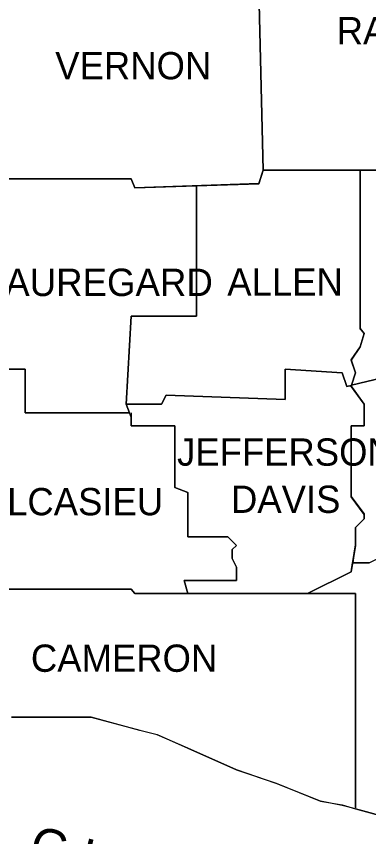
# Model space of a CAD drawing. Extents: x 0.19 to 2.82, y 0.04 to 1.79.
# Drawn here: x 2.26 to 2.3204, y 1.4533 to 1.594 of the extents above; entities that cross this region are included whole.
import ezdxf

# ---------------------------------------------------------------- set-up
doc = ezdxf.new("R2010")
doc.units = 0
for name, color, linetype in [('Dist03', 7, 'Continuous'), ('Dist07', 7, 'Continuous'), ('Dist08', 7, 'Continuous'), ('Standard Info', 7, 'Continuous')]:
    doc.layers.add(name, color=color, linetype=linetype)

msp = doc.modelspace()

# ---------------------------------------------------------------- linework, layer by layer
at = {"layer": 'Dist03'}
for points in [[(2.3469, 1.56308), (2.3454, 1.56308), (2.3454, 1.56758), (2.3439, 1.56917), (2.3424, 1.57067), (2.3424, 1.57292), (2.34015, 1.57292), (2.33782, 1.57292), (2.33557, 1.57367), (2.33482, 1.57592), (2.33407, 1.57592), (2.33257, 1.57517), (2.33182, 1.57367), (2.33024, 1.57217), (2.32799, 1.57067), (2.32649, 1.56758), (2.31899, 1.56758)], [(2.31899, 1.56758), (2.31899, 1.54042), (2.31965, 1.53958), (2.31899, 1.53733), (2.3174, 1.53508), (2.31815, 1.53283), (2.3174, 1.53058)], [(2.31732, 1.53075), (2.31965, 1.5275), (2.31965, 1.526), (2.31965, 1.52375), (2.3174, 1.52375), (2.3174, 1.51167), (2.31965, 1.50867), (2.31965, 1.50783), (2.31815, 1.50633), (2.31815, 1.50333), (2.3174, 1.49875), (2.3099, 1.495)], [(2.3099, 1.495), (2.31815, 1.495), (2.31815, 1.45833)], [(2.31815, 1.45808), (2.32424, 1.45642), (2.33257, 1.45725), (2.34015, 1.45492), (2.34165, 1.45492), (2.3469, 1.45642), (2.34765, 1.45642)]]:
    msp.add_lwpolyline(points, dxfattribs=at)
at = {"layer": 'Dist07'}
for points in [[(2.30232, 1.56758), (2.30157, 1.56533), (2.28032, 1.56458), (2.27965, 1.56608), (2.25765, 1.56608), (2.2539, 1.56383), (2.25007, 1.56683), (2.2494, 1.56533)], [(2.31899, 1.56758), (2.30232, 1.56758)], [(2.3174, 1.53058), (2.31815, 1.53283), (2.3174, 1.53508), (2.31899, 1.53733), (2.31965, 1.53958), (2.31899, 1.54042), (2.31899, 1.56758)], [(2.3099, 1.495), (2.3174, 1.49875), (2.31815, 1.50333), (2.31815, 1.50633), (2.31965, 1.50783), (2.31965, 1.50867), (2.3174, 1.51167), (2.3174, 1.52375), (2.31965, 1.52375), (2.31965, 1.526), (2.31965, 1.5275), (2.31732, 1.53075)], [(2.31815, 1.45833), (2.31815, 1.495), (2.3099, 1.495)], [(2.25915, 1.47383), (2.26824, 1.47383), (2.27282, 1.47383), (2.28115, 1.47158), (2.28415, 1.47083), (2.2894, 1.4685), (2.29774, 1.46475), (2.30457, 1.4625), (2.31215, 1.45942), (2.3159, 1.45875), (2.31815, 1.45808)]]:
    msp.add_lwpolyline(points, dxfattribs=at)
at = {"layer": 'Dist08'}
for points in [[(2.30232, 1.56758), (2.32649, 1.56758), (2.32799, 1.57067), (2.33024, 1.57217), (2.33182, 1.57367), (2.33257, 1.57517), (2.33407, 1.57592), (2.33482, 1.57592), (2.33557, 1.57367), (2.33782, 1.57292), (2.34015, 1.57292), (2.3424, 1.57292)], [(2.2494, 1.56533), (2.25007, 1.56683), (2.2539, 1.56383), (2.25765, 1.56608), (2.27965, 1.56608), (2.28032, 1.56458), (2.30157, 1.56533), (2.30232, 1.56758)]]:
    msp.add_lwpolyline(points, dxfattribs=at)
at = {"layer": 'Standard Info'}
msp.add_line((2.31765, 1.50025), (2.31774, 1.50025), dxfattribs=at)
for points in [[(2.29249, 1.60517), (2.29249, 1.60392), (2.29849, 1.60392), (2.29849, 1.59858), (2.30157, 1.59858), (2.30232, 1.56758)], [(2.29249, 1.60517), (2.29249, 1.60392), (2.29849, 1.60392), (2.29849, 1.59858), (2.30157, 1.59858), (2.30232, 1.56758)], [(2.30232, 1.56758), (2.30157, 1.59858), (2.29849, 1.59858), (2.29849, 1.60392), (2.29249, 1.60392), (2.29249, 1.60517)], [(2.29249, 1.60508), (2.29249, 1.60392), (2.29849, 1.60392), (2.29849, 1.59858), (2.30157, 1.59858), (2.30232, 1.56758)], [(2.3424, 1.57283), (2.34015, 1.57283), (2.33782, 1.57283), (2.33557, 1.57367), (2.33482, 1.57592), (2.33407, 1.57592), (2.33257, 1.57517), (2.33182, 1.57367), (2.33024, 1.57208), (2.32799, 1.57058), (2.32649, 1.56758), (2.30232, 1.56758)], [(2.31899, 1.56758), (2.32649, 1.56758), (2.32799, 1.57058), (2.33024, 1.57208), (2.33182, 1.57367), (2.33257, 1.57517), (2.33407, 1.57592), (2.33482, 1.57592), (2.33557, 1.57367), (2.33782, 1.57283), (2.34015, 1.57283), (2.3424, 1.57283), (2.3424, 1.57058), (2.3439, 1.56908), (2.3454, 1.56758), (2.3454, 1.56308), (2.3469, 1.56308)], [(2.30232, 1.56758), (2.30157, 1.56525), (2.28032, 1.56458), (2.27965, 1.56608), (2.25765, 1.56608), (2.2539, 1.56375), (2.25007, 1.56683), (2.2494, 1.56525)], [(2.2494, 1.56525), (2.25007, 1.56683), (2.2539, 1.56375), (2.25765, 1.56608), (2.27965, 1.56608), (2.28032, 1.56458), (2.2909, 1.56492)], [(2.2909, 1.56492), (2.30157, 1.56525), (2.30232, 1.56758)], [(2.30232, 1.56758), (2.31899, 1.56758)], [(2.3174, 1.5305), (2.31815, 1.53283), (2.3174, 1.535), (2.31899, 1.53733), (2.31965, 1.53958), (2.31899, 1.54033), (2.31899, 1.56758)], [(2.31899, 1.56758), (2.31899, 1.54033), (2.31965, 1.53958), (2.31899, 1.53733), (2.3174, 1.535), (2.31815, 1.53283), (2.31749, 1.53075)], [(2.27882, 1.5275), (2.27965, 1.54258), (2.2909, 1.54258), (2.2909, 1.56492)], [(2.2909, 1.56492), (2.2909, 1.54258), (2.27965, 1.54258), (2.27882, 1.5275), (2.2794, 1.526)], [(2.2794, 1.526), (2.26149, 1.526), (2.26149, 1.5335), (2.2539, 1.5335), (2.2539, 1.526), (2.23649, 1.526)], [(2.23649, 1.526), (2.2539, 1.526), (2.2539, 1.5335), (2.26149, 1.5335), (2.26149, 1.526), (2.2794, 1.526)], [(2.3174, 1.53067), (2.31665, 1.5305), (2.3159, 1.53283), (2.30607, 1.5335), (2.30607, 1.52825), (2.28565, 1.529), (2.2849, 1.5275), (2.27882, 1.5275)], [(2.27882, 1.5275), (2.2849, 1.5275), (2.28565, 1.529), (2.30607, 1.52825), (2.30607, 1.5335), (2.3159, 1.53283), (2.31665, 1.5305), (2.3174, 1.53067)], [(2.32724, 1.532), (2.32274, 1.532), (2.31749, 1.53075)], [(2.31749, 1.53075), (2.32274, 1.532), (2.32799, 1.532), (2.34465, 1.532), (2.34465, 1.52825), (2.34924, 1.52825), (2.34924, 1.52142), (2.35299, 1.51842), (2.35224, 1.51692)], [(2.31732, 1.53067), (2.31965, 1.5275), (2.31965, 1.526), (2.31965, 1.52375), (2.3174, 1.52375), (2.3174, 1.51158), (2.31965, 1.50858), (2.31965, 1.50783), (2.31815, 1.50633), (2.31815, 1.50325), (2.3174, 1.49875), (2.3099, 1.495)], [(2.31774, 1.50025), (2.31815, 1.50325), (2.31815, 1.50633), (2.31965, 1.50783), (2.31965, 1.50858), (2.3174, 1.51158), (2.3174, 1.52375), (2.31965, 1.52375), (2.31965, 1.526), (2.31965, 1.5275), (2.31732, 1.53067)], [(2.27965, 1.52375), (2.27965, 1.52525), (2.27882, 1.5275)], [(2.27965, 1.526), (2.27965, 1.52375)], [(2.2894, 1.495), (2.28874, 1.49725), (2.29774, 1.49725), (2.29774, 1.4995), (2.29699, 1.501), (2.29699, 1.50258), (2.29774, 1.50325), (2.29624, 1.50475), (2.2894, 1.50475), (2.2894, 1.51233), (2.28715, 1.51317), (2.28715, 1.52375), (2.27965, 1.52375)], [(2.27965, 1.52375), (2.28715, 1.52375), (2.28715, 1.51317), (2.2894, 1.51233), (2.2894, 1.50475), (2.29624, 1.50475), (2.29774, 1.50325), (2.29699, 1.50258), (2.29699, 1.501), (2.29774, 1.4995), (2.29774, 1.49725), (2.28874, 1.49725), (2.2894, 1.495)], [(2.31765, 1.50025), (2.32049, 1.50025), (2.32199, 1.501), (2.32424, 1.4995), (2.32499, 1.4995), (2.32574, 1.49875), (2.32799, 1.49725), (2.32957, 1.4965), (2.33182, 1.4965), (2.33332, 1.4965), (2.33557, 1.498), (2.33632, 1.49875), (2.33707, 1.4995), (2.33857, 1.50175), (2.34015, 1.50325), (2.34165, 1.50408)], [(2.31815, 1.45867), (2.31815, 1.495), (2.3099, 1.495), (2.3174, 1.49875), (2.31765, 1.50025)], [(2.32049, 1.50025), (2.31765, 1.50025)], [(2.2894, 1.495), (2.28032, 1.495), (2.27965, 1.49575), (2.2494, 1.49575), (2.24557, 1.4965), (2.23424, 1.4965)], [(2.23424, 1.4965), (2.24557, 1.4965), (2.2494, 1.49575), (2.27965, 1.49575), (2.28032, 1.495), (2.3099, 1.495)], [(2.3099, 1.495), (2.2894, 1.495)], [(2.3099, 1.495), (2.31815, 1.495), (2.31815, 1.45825)], [(2.31815, 1.45808), (2.3159, 1.45867), (2.31215, 1.45942), (2.30457, 1.46242), (2.29774, 1.46475), (2.2894, 1.4685), (2.28415, 1.47075), (2.28115, 1.4715), (2.27282, 1.47383), (2.26824, 1.47383), (2.25915, 1.47383)], [(2.34765, 1.45642), (2.3469, 1.45642), (2.34165, 1.45492), (2.34015, 1.45492), (2.33257, 1.45717), (2.32424, 1.45642), (2.31815, 1.45808)]]:
    msp.add_lwpolyline(points, dxfattribs=at)

# ---------------------------------------------------------------- texts
for s, height, p in [('RAPIDES', 0.004679, (2.31494, 1.58917)), ('VERNON', 0.004679, (2.26664, 1.58317)), ('BEAUREGARD', 0.0047, (2.24968, 1.54601)), ('ALLEN', 0.004679, (2.29616, 1.54608)), ('JEFFERSON', 0.004679, (2.28754, 1.51692)), ('DAVIS', 0.004679, (2.2968, 1.50883)), ('CALCASIEU', 0.004679, (2.24969, 1.50842)), ('CAMERON', 0.004679, (2.26246, 1.48158))]:
    msp.add_text(s, height=height, dxfattribs=at).set_placement(p)
msp.add_text('G U L F   O F   M E X I C O', height=0.0062, rotation=345.6507, dxfattribs=at).set_placement((2.26182, 1.4493))

doc.saveas('drawing.dxf')
